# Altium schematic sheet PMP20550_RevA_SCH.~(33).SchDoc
size 431 x 279 mm; Date: Not shown in title block; ApprovedBy: Not shown in title block; CheckedBy: Not shown in title block; Author: Not shown in title block; CompanyName: Not shown in title block; Engineer: Not shown in title block; Organization: Not shown in title block; Address1: Not shown in title block; Address2: Not shown in title block; Address3: Not shown in title block; Address4: Not shown in title block; DocumentNumber: 1; Revision: Use project parameter SCH_Rev; SheetNumber: 2; SheetTotal: 3; PageSetup: Record=PageOptions¦CenterHorizontal=True¦CenterVertical=True¦PrintScale=1.00¦XCorrection=1.00¦YCorrection=1.00¦PrintKind=0¦BorderSize=5000000¦LeftOffset=0¦BottomOffset=0¦Orientation=2¦PaperLength=1000¦PaperWidth=1000¦Scale=100¦PaperSource=15¦PrintQuality=600¦MediaType=1¦DitherType=10¦PaperKind=Letter¦PrintScaleMode=1
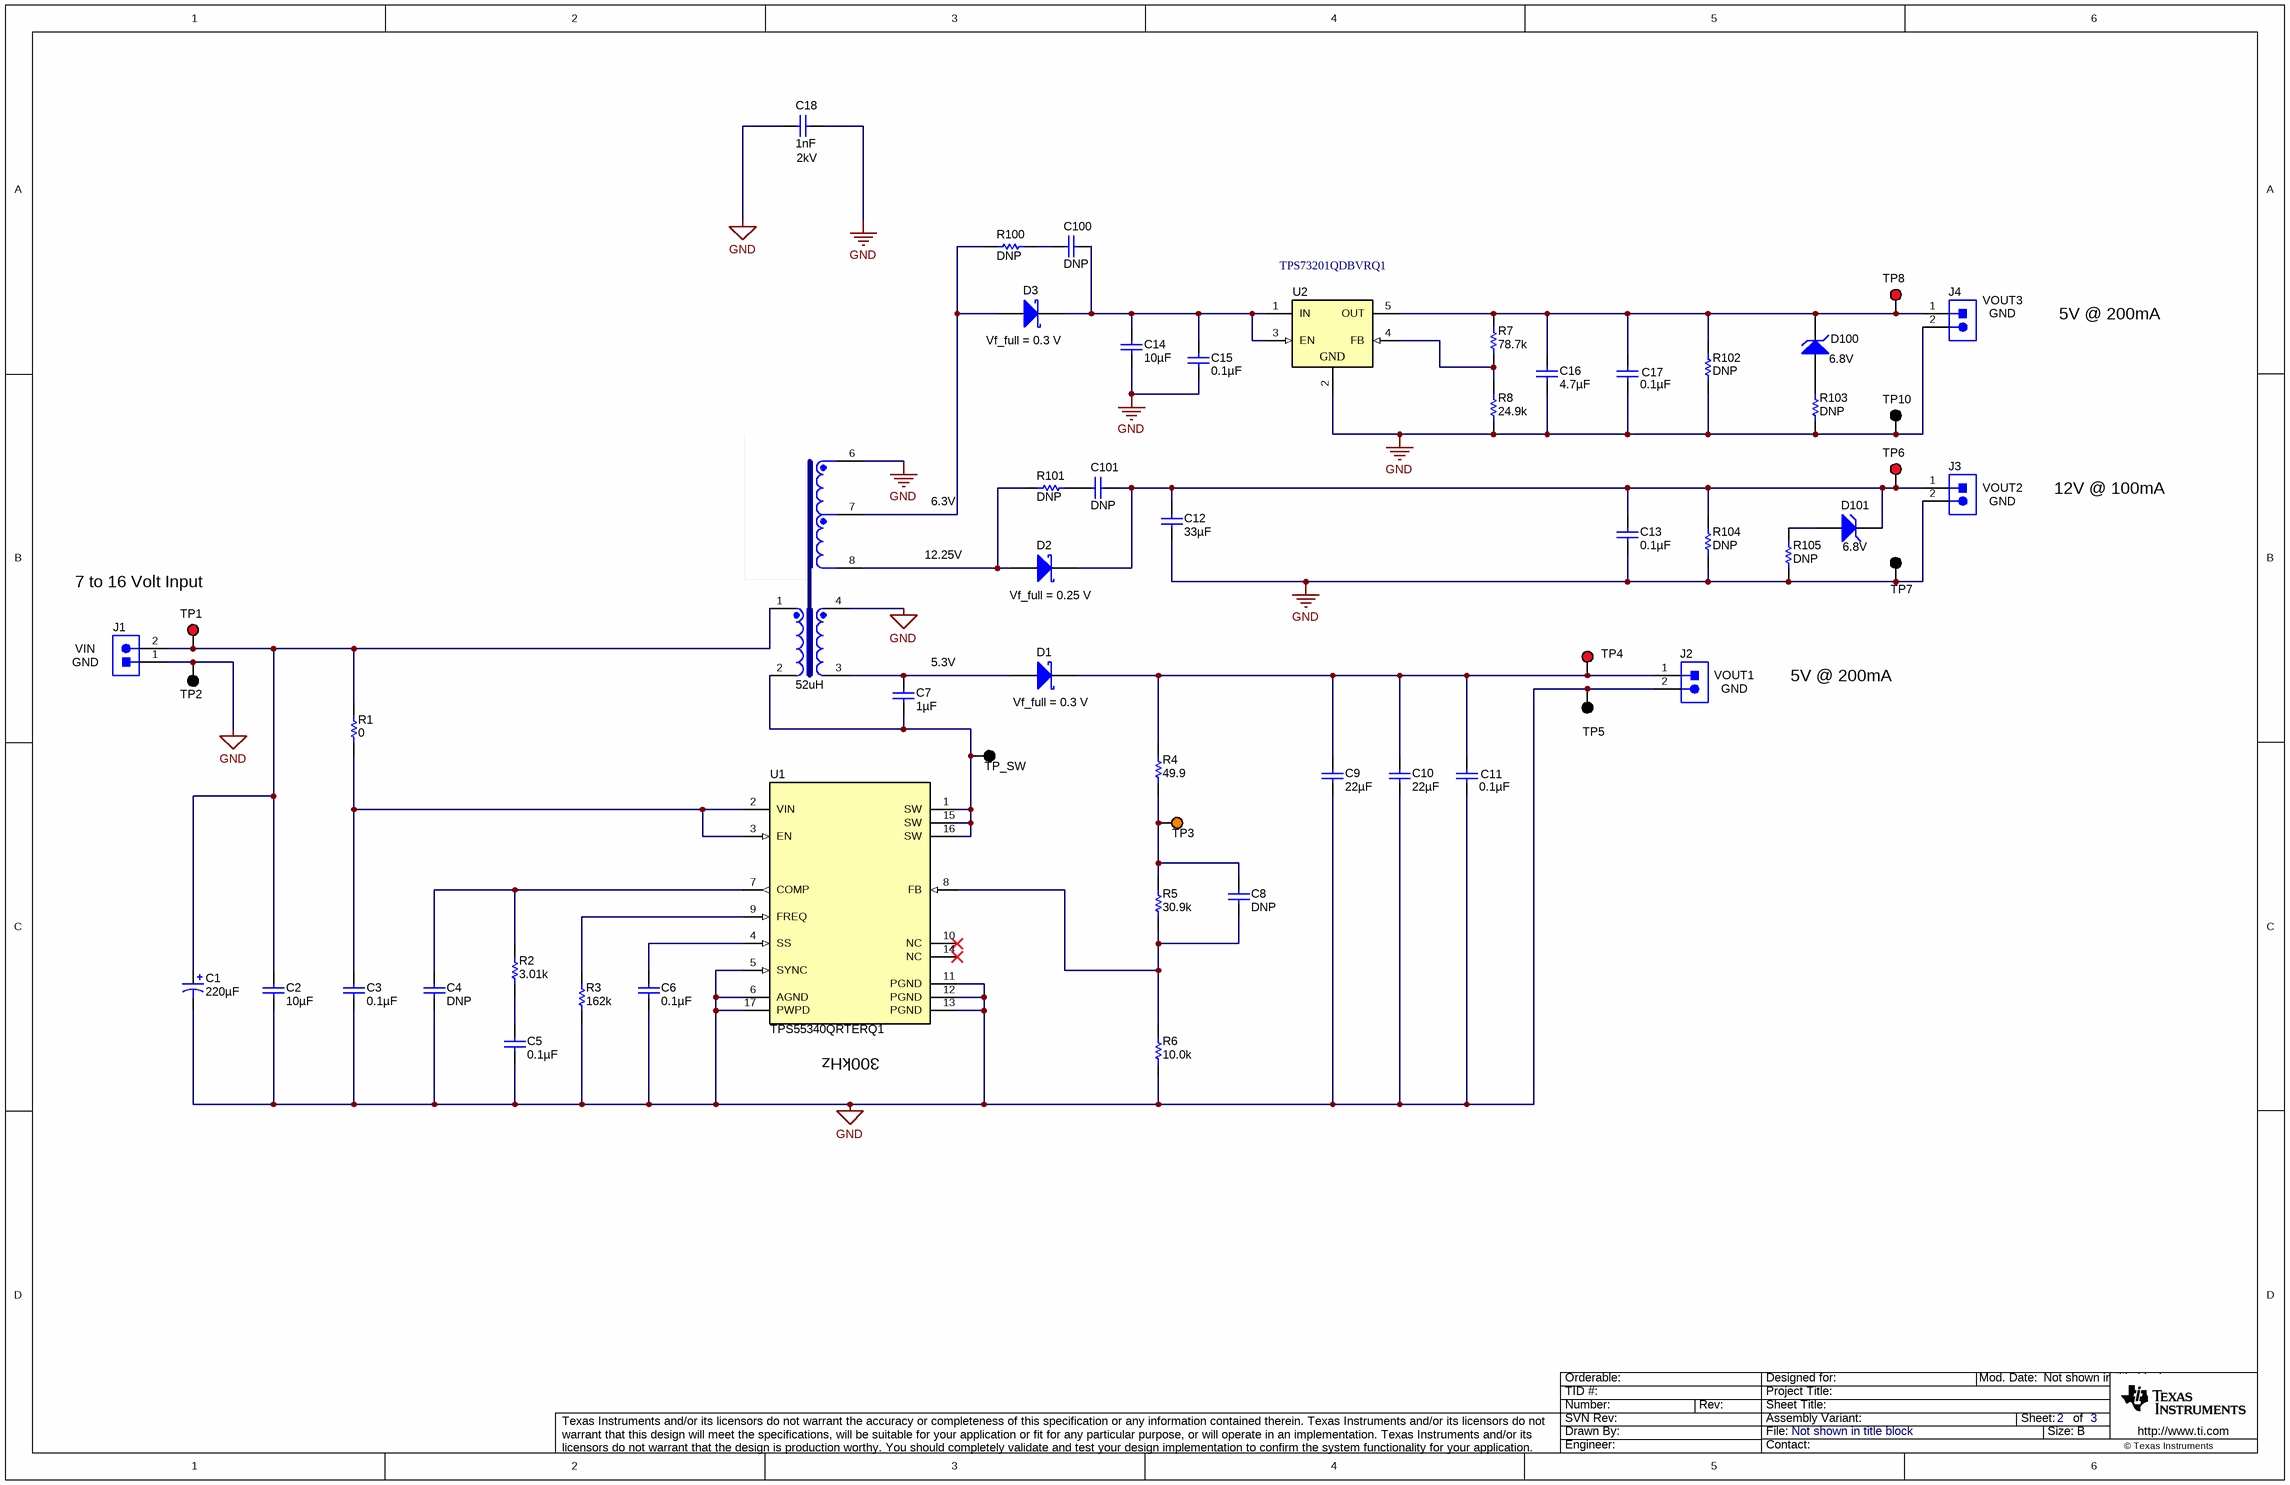
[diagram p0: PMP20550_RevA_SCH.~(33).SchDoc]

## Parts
C1  ValueDisplayed: 220µF  [SM_RADIAL_G]  (hidden comment: EEE-FC1V221P)
C2  ValueDisplayed: 10µF  [1206]  (hidden comment: GMK316AB7106KL)
C3  ValueDisplayed: 0.1µF  [0603]  (hidden comment: C1608X7R1E104K080AA)
C4  ValueDisplayed: DNP  [0402]  (hidden comment: GRM155R71E333KA88D)
C5  ValueDisplayed: 0.1µF  [0603]  (hidden comment: C1608X7R1E104K080AA)
C6  ValueDisplayed: 0.1µF  [0603]  (hidden comment: C1608X7R1E104K080AA)
C7  ValueDisplayed: 1µF  [0805_HV]  (hidden comment: LMK212B7105KG-T)
C8  ValueDisplayed: DNP  [0402]  (hidden comment: GRM1555C1H201JA01D)
C9  ValueDisplayed: 22µF  [0805_HV]  (hidden comment: GRM21BZ71A226ME15L)
C10  ValueDisplayed: 22µF  [0805_HV]  (hidden comment: GRM21BZ71A226ME15L)
C11  ValueDisplayed: 0.1µF  [0603]  (hidden comment: C0603X104K8RACTU)
C12  ValueDisplayed: 33µF  [1206_180]  (hidden comment: C3216X5R1E336M160AC)
C13  ValueDisplayed: 0.1µF  [0805_HV]  (hidden comment: 08053C104KAT2A)
C14  ValueDisplayed: 10µF  [0603]  (hidden comment: GRM188Z71A106MA73D)
C15  ValueDisplayed: 0.1µF  [0603]  (hidden comment: C1608X7R1E104K080AA)
C16  ValueDisplayed: 4.7µF  [0805_HV]  (hidden comment: C2012X7R1E474K125AA)
C17  ValueDisplayed: 0.1µF  [0603]  (hidden comment: C0603X104K8RACTU)
C18  ValueDisplayed: 1nF  Value2: 2kV  [1812]  (hidden comment: GR443QR73D102KW01L)
C100  ValueDisplayed: DNP  [0603]  (hidden comment: GRM1885C1H111JA01D)
C101  ValueDisplayed: DNP  [0603]  (hidden comment: GRM1885C1H111JA01D)
D1  PMEG2020EJ,115  [SOD-323F]  (value not drawn)
D2  PMEG2020EJ,115  [SOD-323F]  (value not drawn)
D3  PMEG2020EJ,115  [SOD-323F]  (value not drawn)
D100  value 6.8V  [SOD-323]  (hidden comment: MMSZ5235BS-7-F)
D101  value 6.8V  [SOD-323]  (hidden comment: MMSZ5235BS-7-F)
J1  PEC02SAAN  [CONN_PEC02SAAN]  (value not drawn)
J2  PEC02SAAN  [CONN_PEC02SAAN]  (value not drawn)
J3  PEC02SAAN  [CONN_PEC02SAAN]  (value not drawn)
J4  PEC02SAAN  [CONN_PEC02SAAN]  (value not drawn)
R1  ValueDisplayed: 0  [0603]  (hidden comment: ERJ-3GEY0R00V)
R2  ValueDisplayed: 3.01k  [0603]  (hidden comment: RC0603FR-073K01L)
R3  ValueDisplayed: 162k  [0603]  (hidden comment: CRCW0603162KFKEA)
R4  ValueDisplayed: 49.9  [0402]  (hidden comment: ERJ-2RKF49R9X)
R5  ValueDisplayed: 30.9k  [0603]  (hidden comment: CRCW060330K9FKEA)
R6  ValueDisplayed: 10.0k  [0402]  (hidden comment: ERJ-2RKF1002X)
R7  ValueDisplayed: 78.7k  [0603]  (hidden comment: RC0603FR-0778K7L)
R8  ValueDisplayed: 24.9k  [0603]  (hidden comment: CRCW060324K9FKEA)
R100  ValueDisplayed: DNP  [0603]  (hidden comment: CPF0603B1K62E)
R101  ValueDisplayed: DNP  [0603]  (hidden comment: CPF0603B1K62E)
R102  ValueDisplayed: DNP  [0603]  (hidden comment: CPF0603B1K62E)
R103  ValueDisplayed: DNP  [0603]  (hidden comment: CPF0603B1K62E)
R104  ValueDisplayed: DNP  [0603]  (hidden comment: CPF0603B1K62E)
R105  ValueDisplayed: DNP  [0603]  (hidden comment: CPF0603B1K62E)
T1  ValueDisplayed: 52uH  [GCI_UU9_8H-132LF]  (hidden comment: UU9.8H-132LF)
T?  59487  [Payton_59487]  (value not drawn)
TP1  5000  [Keystone5000]  (value not drawn)
TP2  5001  [Keystone5001]  (value not drawn)
TP3  5003  [Keystone5003]  (value not drawn)
TP4  VBUS  [Keystone5000]  (value not drawn)
TP5  5001  [Keystone5001]  (value not drawn)
TP6  5000  [Keystone5000]  (value not drawn)
TP7  5001  [Keystone5001]  (value not drawn)
TP8  5000  [Keystone5000]  (value not drawn)
TP10  5001  [Keystone5001]  (value not drawn)
TP_SW  5001  [Keystone5001]  (value not drawn)
U1  TPS55340QRTERQ1  [RTE0016C]
U2  TPS73201QDBVRQ1  [DBV0005A_N]

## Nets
GND: C1.2(-) C2.2 C3.2 C4.2 C5.2 C6.2 C9.2 C10.2 C11.2 C12.2 C13.2 C14.2 C15.2 C16.2 C17.2 C18.1 C18.2 J1.1 J2.2 J3.2 J4.2 R3.1 R6.1 R8.1 R102.2 R103.2 R104.2 R105.2 T1.4 T?.6 TP2.1 TP5.1 TP7.1 TP10.1 U1.5(SYNC) U1.6(AGND) U1.11(PGND) U1.12(PGND) U1.13(PGND) U1.17(PWPD) U2.2(GND)
NetC1_1: C1.1(+) C2.1 J1.2 R1.2 T1.1 TP1.1
NetC3_1: C3.1 R1.1 U1.2(VIN) U1.3(EN)
NetC4_1: C4.1 R2.2 U1.7(COMP)
NetC5_1: C5.1 R2.1
NetC6_1: C6.1 U1.4(SS)
NetC7_1: C7.1 D1.2(A) T1.3
NetC7_2: C7.2 T1.2 TP_SW.1 U1.1(SW) U1.15(SW) U1.16(SW)
NetC8_1: C8.1 R4.1 R5.2 TP3.1
NetC8_2: C8.2 R5.1 R6.2 U1.8(FB)
NetC9_1: C9.1 C10.1 C11.1 D1.1(K) J2.1 R4.2 TP4.1
NetC12_1: C12.1 C13.1 C101.1 D2.1(K) D101.1(K) J3.1 R104.1 TP6.1
NetC14_1: C14.1 C15.1 C100.1 D3.1(K) U2.1(IN) U2.3(EN)
NetC16_1: C16.1 C17.1 D100.1(K) J4.1 R7.2 R102.1 TP8.1 U2.5(OUT)
NetC100_2: C100.2 R100.1
NetC101_2: C101.2 R101.1
NetD2_2: D2.2(A) R101.2 T?.8
NetD3_2: D3.2(A) R100.2 T?.7
NetD100_2: D100.2(A) R103.1
NetD101_2: D101.2(A) R105.1
NetR3_2: R3.2 U1.9(FREQ)
NetR7_1: R7.1 R8.2 U2.4(FB)

Not connected (* = marked no-connect by the designer): U1 10(NC)* 14(NC)*

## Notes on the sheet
- (near J4) VOUT3
- (near D3) Vf_full = 0.3 V
- (near J4) GND
- 5V @ 200mA
- 6.3V
- (near J3) VOUT2
- (near J3) GND
- 12V @ 100mA
- 12.25V
- 7 to 16 Volt Input
- (near D2) Vf_full = 0.25 V
- (near J1) VIN
- (near J1) GND
- (near C7) 5.3V
- (near D1) Vf_full = 0.3 V
- (near J2) VOUT1
- (near J2) GND
- (near U1) 300kHz

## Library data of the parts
C1 = EEE-FC1V221P: CAP, AL, 220 µF, 35 V, +/- 20%, 0.15 ohm, SMD; Manufacturer: Panasonic; Polarized: Y; CompType: Capacitor; Value: 220uF; U/M: EA; Cap_F: 0.00022; Tolerance_%: 20; VDC_V: 35; Value2: 35V; ESR_ohm: 0.15; IRMS_A: 0.67; TaMin_C: -40; TaMax_C: 105; Cap_Case: G; SizeAreaWB_mm2: 172.2; SizeArea_mm2: 123.6; SizeX_mm: 12; SizeY_mm: 10.3; SizeZ_mm: 10.2; AEC Category: Q200
C2 = GMK316AB7106KL: CAP, CERM, 10 µF, 35 V, +/- 10%, X7R, 1206; Manufacturer: Taiyo Yuden; Polarized: N; CompType: Capacitor; Value: 10uF; U/M: EA; Cap_F: 0.00001; Tolerance_%: 10; Value1: Unknown; VDC_V: 35; Value2: 35V; TaMin_C: -55; TaMax_C: 125; SizeArea_mm2: 5.12; SizeAreaWB_mm2: 10.92; SizeX_mm: 3.2; SizeY_mm: 1.6; SizeZ_mm: 1.35; AEC Category: Q200
C3 C5 C6 C15 = C1608X7R1E104K080AA: CAP, CERM, 0.1 µF, 25 V, +/- 10%, X7R, 0603; Manufacturer: TDK; Polarized: N; CompType: Capacitor; Value: 0.1uF; U/M: EA; Cap_F: 0.0000001; Tolerance_%: 10; Value1: Unknown; VDC_V: 25; Value2: 25V; TaMin_C: -55; TaMax_C: 125; SizeArea_mm2: 1.28; SizeAreaWB_mm2: 4.68; SizeX_mm: 1.6; SizeY_mm: 0.8; SizeZ_mm: 1; AEC Category: Q200
C4 = GRM155R71E333KA88D: OPEN, 0402; Manufacturer: MuRata; Polarized: N; CompType: Capacitor; U/M: EA; Cap_F: 0.000000033; Tolerance_%: 10; Value1: Unknown; VDC_V: 25; Value2: 25V; TempCo: X7R; TaMin_C: -55; TaMax_C: 125; SizeArea_mm2: 0.5; SizeAreaWB_mm2: 3; SizeX_mm: 1; SizeZ_mm: 0.6; AEC Category: Q200
C7 = LMK212B7105KG-T: CAP, CERM, 1 µF, 10 V, +/- 10%, X7R, 0805; Manufacturer: Taiyo Yuden; Polarized: N; CompType: Capacitor; Value: 1uF; U/M: EA; Cap_F: 0.000001; Tolerance_%: 10; Value1: Unknown; Value2: 10V; TaMin_C: -55; TaMax_C: 125; Cap_Case: 0805; SizeArea_mm2: 2.5; SizeAreaWB_mm2: 6.75; SizeX_mm: 2; SizeY_mm: 1.25; SizeZ_mm: 1.45; AEC Category: Q200
C8 = GRM1555C1H201JA01D: CAP, CERM, 200 pF, 50 V, +/- 5%, C0G/NP0, 0402; Manufacturer: MuRata; Polarized: N; CompType: Capacitor; Value: 200pF; U/M: EA; Cap_F: 0.0000000002; Tolerance_%: 5; Value1: Unknown; VDC_V: 50; Value2: 50V; TaMin_C: -55; TaMax_C: 125; SizeArea_mm2: 0.5; SizeAreaWB_mm2: 3; SizeX_mm: 1; SizeZ_mm: 0.6; AEC Category: Q200
C9 C10 = GRM21BZ71A226ME15L: CAP, CERM, 22 µF, 10 V, +/- 20%, X7R, 0805; Manufacturer: MuRata; Polarized: N; CompType: Capacitor; Value: 22uF; U/M: EA; Cap_F: 0.000022; Tolerance_%: 20; Value1: Unknown; VDC_V: 10; Value2: 10V; TaMin_C: -55; TaMax_C: 125; Cap_Case: 0805; SizeArea_mm2: 2.5; SizeAreaWB_mm2: 6.75; SizeX_mm: 2; SizeY_mm: 1.25; SizeZ_mm: 1.45; AEC Category: Q200
C11 C17 = C0603X104K8RACTU: CAP, CERM, 0.1 µF, 10 V, +/- 10%, X7R, 0603; Manufacturer: Kemet; Polarized: N; CompType: Capacitor; Value: 0.1uF; U/M: EA; Cap_F: 0.0000001; Tolerance_%: 10; Value1: Unknown; Value2: 10V; TaMin_C: -55; TaMax_C: 125; SizeArea_mm2: 1.28; SizeAreaWB_mm2: 4.68; SizeX_mm: 1.6; SizeY_mm: 0.8; SizeZ_mm: 1; AEC Category: Q200
C12 = C3216X5R1E336M160AC: CAP, CERM, 33 µF, 25 V, +/- 20%, X5R, 1206; Manufacturer: TDK; Polarized: N; CompType: Capacitor; Value: 33uF; U/M: EA; Cap_F: 0.000033; Tolerance_%: 20; ESR_ohm: 0.002648; Value1: 0.002648 ohm; VDC_V: 25; Value2: 25V; IRMS_A: 4.45864; TaMin_C: -55; TaMax_C: 85; SizeArea_mm2: 5.12; SizeAreaWB_mm2: 10.92; SizeX_mm: 3.2; SizeY_mm: 1.6; SizeZ_mm: 1.8; AEC Category: Q200
C13 = 08053C104KAT2A: CAP, CERM, 0.1 µF, 25 V, +/- 10%, X7R, 0805; Manufacturer: AVX; Polarized: N; CompType: Capacitor; Value: 0.1uF; U/M: EA; Cap_F: 0.0000001; Tolerance_%: 10; ESR_ohm: 0.28; Value1: 0.28 ohm; VDC_V: 25; Value2: 25V; TaMin_C: -55; TaMax_C: 125; Cap_Case: 0805; SizeArea_mm2: 2.5; SizeAreaWB_mm2: 6.75; SizeX_mm: 2; SizeY_mm: 1.25; SizeZ_mm: 1.45; AEC Category: Q200
C14 = GRM188Z71A106MA73D: CAP, CERM, 10 µF, 10 V, +/- 20%, X7R, 0603; Manufacturer: MuRata; Polarized: N; CompType: Capacitor; Value: 10uF; U/M: EA; Cap_F: 0.00001; Tolerance_%: 20; Value1: Unknown; VDC_V: 10; Value2: 10V; TaMin_C: -55; TaMax_C: 125; SizeArea_mm2: 1.28; SizeAreaWB_mm2: 4.68; SizeX_mm: 1.6; SizeY_mm: 0.8; SizeZ_mm: 1; AEC Category: Q200
C16 = C2012X7R1E474K125AA: CAP, CERM, 4.7 µF, 25 V, +/- 10%, X7R, 0805; Manufacturer: TDK; Polarized: N; CompType: Capacitor; Value: 4.7uF; U/M: EA; Cap_F: 0.0000047; Tolerance_%: 10; Value1: Unknown; VDC_V: 25; Value2: 25V; TaMin_C: -55; TaMax_C: 125; Cap_Case: 0805; SizeArea_mm2: 2.5; SizeAreaWB_mm2: 6.75; SizeX_mm: 2; SizeY_mm: 1.25; SizeZ_mm: 1.45; AEC Category: Q200
C18 = GR443QR73D102KW01L: CAP, CERM, 1000 pF, 2000 V, +/- 10%, X7R, 1812; Manufacturer: MuRata; Polarized: N; CompType: Capacitor; Value: 1000pF; U/M: EA; Cap_F: 0.000000001; Tolerance_%: 10; Value1: Unknown; VDC_V: 2000; TaMin_C: -55; TaMax_C: 125; SizeArea_mm2: 14.4; SizeAreaWB_mm2: 23.1; SizeX_mm: 4.5; SizeY_mm: 3.2; SizeZ_mm: 1.35; AEC Category: Q200
C100 C101 = GRM1885C1H111JA01D: CAP, CERM, 110 pF, 50 V, +/- 5%, C0G/NP0, 0603; Manufacturer: MuRata; Polarized: N; CompType: Capacitor; Value: 110pF; U/M: EA; Cap_F: 0.00000000011; Tolerance_%: 5; Value1: Unknown; VDC_V: 50; Value2: 50V; TaMin_C: -55; TaMax_C: 125; SizeArea_mm2: 1.28; SizeAreaWB_mm2: 4.68; SizeX_mm: 1.6; SizeY_mm: 0.8; SizeZ_mm: 1; AEC Category: Q200
D1-D3 = PMEG2020EJ,115: Diode, Schottky, 20 V, 2 A, SOD-323F; Manufacturer: NXP Semiconductor; U/M: EA; Vf_V: 0.525; Value: 20V; Value1: 2A; Value2: 0.525V; Io_A: 2; Vr_V: 20; TJmax_C: 150; SizeAreaWB_mm2: 7.875; SizeArea_mm2: 3.125; SizeX_mm: 2.5; SizeY_mm: 1.25; SizeZ_mm: 0.8; AEC Category: Q101; AEC Qualified: N
D100 D101 = MMSZ5235BS-7-F: Diode, Zener, 6.8 V, 200 mW, SOD-323; Manufacturer: Diodes Inc.; SymbolCreator: a0412235; U/M: EA; Power_W: 0.2; Vz_V: 6.8; Value1: 0.2W; RJA_CperW: 350; SizeAreaWB_mm2: 8.695; SizeArea_mm2: 3.645; SizeX_mm: 2.7; SizeY_mm: 1.35; SizeZ_mm: 1; AEC Category: Q101
J1-J4 = PEC02SAAN: Header, 100mil, 2x1, Tin, TH; Manufacturer: Sullins Connector Solutions; SymbolCreator: a0412235; Pitch_mm: 2.54; Gender: Male; Shrouded: N; Row_Count: 1; Current_A: 3; Voltage_V: 1800; Cert_UL: Y
R1 = ERJ-3GEY0R00V: RES, 0, 5%, 0.1 W, 0603; Manufacturer: Panasonic; CompType: Resistor; Value: 0; Value_Code: 0000; Tolerance_%: 5; Power_W: 0.1; Value2: 0.1W; VDC_V: 50; TempCo: 600 ppm/C; SizeArea_mm2: 1.28; SizeX_mm: 1.6; SizeY_mm: 0.8; SizeZ_mm: 1; EIA_Code: E24; U/M: EA; AEC Category: Q200
R2 = RC0603FR-073K01L: RES, 3.01 k, 1%, 0.1 W, 0603; Manufacturer: Yageo America; CompType: Resistor; Value: 3.01k; Res_ohm: 3010; Value_Code: 3k01; Tolerance_%: 1; Power_W: 0.1; Value2: 0.1W; VDC_V: 150; TempCo: 200 ppm/C; SizeArea_mm2: 1.28; SizeX_mm: 1.6; SizeY_mm: 0.8; EIA_Code: E96; U/M: EA; AEC Category: Q200
R3 = CRCW0603162KFKEA: RES, 162 k, 1%, 0.1 W, 0603; Manufacturer: Vishay-Dale; CompType: Resistor; Value: 162k; Res_ohm: 162000; Tolerance_%: 1; Power_W: 0.1; Value2: 0.1W; VDC_V: 75; TempCo: 100 ppm/C; SizeArea_mm2: 1.28; SizeX_mm: 1.6; SizeY_mm: 0.8; EIA_Code: E96; U/M: EA; AEC Category: Q200
R4 = ERJ-2RKF49R9X: RES, 49.9, 1%, 0.1 W, AEC-Q200 Grade 0, 0402; Manufacturer: Panasonic; CompType: Resistor; Value: 49.9; Value_Code: 49R9; Tolerance_%: 1; Power_W: 0.1; Value2: 0.1W; VDC_V: 50; TempCo: 100 ppm/C; SizeArea_mm2: 0.5; SizeZ_mm: 0.6; EIA_Code: E96; U/M: EA; AEC Category: Q200; AEC Qualified: Y; AEC Grade: 0
R5 = CRCW060330K9FKEA: RES, 30.9 k, 1%, 0.1 W, 0603; Manufacturer: Vishay-Dale; CompType: Resistor; Value: 30.9k; Res_ohm: 30900; Value_Code: 30k9; Tolerance_%: 1; Power_W: 0.1; Value2: 0.1W; VDC_V: 75; TempCo: 100 ppm/C; SizeArea_mm2: 1.28; SizeX_mm: 1.6; SizeY_mm: 0.8; EIA_Code: E96; U/M: EA; AEC Category: Q200
R6 = ERJ-2RKF1002X: RES, 10.0 k, 1%, 0.1 W, 0402; Manufacturer: Panasonic; CompType: Resistor; Value: 10.0k; Res_ohm: 10000; Value_Code: 10k0; Tolerance_%: 1; Power_W: 0.1; Value2: 0.1W; VDC_V: 50; TempCo: 100 ppm/C; SizeArea_mm2: 0.5; SizeZ_mm: 0.6; EIA_Code: E96; U/M: EA; AEC Category: Q200
R7 = RC0603FR-0778K7L: RES, 78.7 k, 1%, 0.1 W, 0603; Manufacturer: Yageo America; CompType: Resistor; Value: 78.7k; Res_ohm: 78700; Value_Code: 78k7; Tolerance_%: 1; Power_W: 0.1; Value2: 0.1W; VDC_V: 150; TempCo: 200 ppm/C; SizeArea_mm2: 1.28; SizeX_mm: 1.6; SizeY_mm: 0.8; EIA_Code: E96; U/M: EA; AEC Category: Q200
R8 = CRCW060324K9FKEA: RES, 24.9 k, 1%, 0.1 W, 0603; Manufacturer: Vishay-Dale; CompType: Resistor; Value: 24.9k; Res_ohm: 24900; Value_Code: 24k9; Tolerance_%: 1; Power_W: 0.1; Value2: 0.1W; VDC_V: 75; TempCo: 100 ppm/C; SizeArea_mm2: 1.28; SizeX_mm: 1.6; SizeY_mm: 0.8; EIA_Code: E96; U/M: EA; AEC Category: Q200
R100-R105 = CPF0603B1K62E: RES, 1.62 k, 0.1%, 0.063 W, 0603; Manufacturer: TE Connectivity; CompType: Resistor; Value: 1.62k; Res_ohm: 1620; Value_Code: 1k62; Tolerance_%: 0.1; Power_W: 0.063; Value2: 0.063W; VDC_V: 50; TempCo: 25 ppm/C; SizeArea_mm2: 1.28; SizeX_mm: 1.6; SizeY_mm: 0.8; SizeZ_mm: 1; EIA_Code: E192; U/M: EA; AEC Category: Q200
T1 = UU9.8H-132LF: Transformer, 1.3 mH, TH; Manufacturer: GCI Technologies; SymbolCreator: Altium; Value: 1.3mH; Lp: 1300; DCR_ohm: 0.5
T? = 59487: Transformer, TH; Manufacturer: Payton; SymbolCreator: Altium; Ns1toNp: 0.25; SizeAreaWB_mm2: 1512; SizeArea_mm2: 1360; SizeX_mm: 40; SizeY_mm: 34; SizeZ_mm: 12.7
TP1 TP6 TP8 = 5000: Test Point, Miniature, Red, TH; Manufacturer: Keystone; CompType: Test Point Loop; ContactFinish: Silver
TP2 TP5 TP7 TP10 TP_SW = 5001: Test Point, Miniature, Black, TH; Manufacturer: Keystone; CompType: Test Point Loop; ContactFinish: Silver
TP3 = 5003: Test Point, Miniature, Orange, TH; Manufacturer: Keystone; CompType: Test Point Loop; ContactFinish: Silver
TP4 = 5000: Test Point, TH, Miniature, Red; Manufacturer: Keystone; CompType: Test Point Loop; U/M: EA
U1 = TPS55340QRTERQ1: Integrated 5-A 40-V Wide Input Range Boost/SEPIC/Flyback DC-DC Regulator, RTE0016C; Alternate PartNumber: TPS55340QRTETQ1; Manufacturer: Texas Instruments; SymbolCreator: x0208326; SizeArea_mm2: 9; SizeAreaWB_mm2: 16; SizeX_mm: 3; SizeZ_mm: 0.8; CompType: IC; U/M: EA
U2 = TPS73201QDBVRQ1: Single Output Fast Transient Response LDO, 250 mA, Adjustable 1.2 to 5.5 V Output, 1.7 to 5.5 V Input, 5-pin SOT-23 (DBV), -40 to 125 degC, Green (RoHS & no Sb/Br); Manufacturer: Texas Instruments; Alternate PartNumber: Equivalent; Accuracy(%): 1; Iout(Max)(A): 0.25; Iq(Typ)(mA): 0.4; Rating: Automotive; SubFamily: Single Channel LDO; Vin(Max)(V): 5.5; Vin(Min)(V): 1.7; Vout Adj(Min)(V): 1.2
